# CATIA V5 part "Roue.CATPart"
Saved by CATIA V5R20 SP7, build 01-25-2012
Part number: Roue
Bounding box of the stored display mesh (mm): x 160 to 250, y -100 to 100, z -100 to 100
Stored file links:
  D:\thinkmotion-MPB\Dropbox\IAO_2011\MMS_GR3\IAO_2011_1501_ybellafdil\Roue.CATPart
  D:\thinkmotion-MPB\Dropbox\IAO_2011\MMS_GR3\IAO_2011_1501_ybellafdil\Assemblage Final.CATProduct
  D:\thinkmotion-MPB\Dropbox\IAO_2011\MMS_GR3\IAO_2011_1501_ybellafdil\SKL Roue.CATPart
  D:\thinkmotion-MPB\Dropbox\IAO_2011\MMS_GR3\IAO_2011_1501_ybellafdil\SKL Bati.CATPart
  D:\thinkmotion-MPB\Dropbox\IAO_2011\MMS_GR3\IAO_2011_1501_ybellafdil\Bati.CATPart
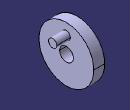
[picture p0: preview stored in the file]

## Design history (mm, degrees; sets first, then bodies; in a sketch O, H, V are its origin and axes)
Parameters
  `Rayon roue` = 100 mm
  `Excentricité ` = 60 mm
  `Rayon excentrique` = 15 mm
  `Longueur Excentrique` = 50 mm
External parameters (linked from other documents)
  `External.Rayon guidage roue` = 25 mm
Set1
  Plane1: linked copy from another document
  Point1: linked copy from another document
Body1 (main body)
  Sketch1 on Plane1, origin (0, 0, 0), H (0, 1, 0), V (0, 0, 1)
    circle A1 centre (0, 0) radius 100
    point P1 (0, 0)
    reference projected point E1 (0, 0) from Point1
    circle A2 centre (0, 0) radius 25
    point P2 (0, 0)
    reference projected point E2 (0, 0) from Point1
    radius A1 = 100 {= `Rayon roue`}
    radius A2 = 25 {= `External.Rayon guidage roue`}
    coincidence: P1 V, E1 P1, P2 E2
  Pad1: profile Sketch1, direction (-1, 0, 0), length -160, opposite side length 200
  Sketch2 on start face of Pad1, origin (200, 0, 0), H (0, 1, 0), V (0, 0, 1)
    circle A1 centre (0, 60) radius 15
    point P1 (0, 60)
    radius A1 = 15 {= `Rayon excentrique`}
    distance P1 H = 60 {= `Excentricité `}
    coincidence: P1 V
  Pad2: profile Sketch2, direction (1, 0, 0), length 50 {= `Longueur Excentrique`}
